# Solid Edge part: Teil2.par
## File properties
Author: administrator
Template: Normal.par
Last saved by: administrator
Revision: 1
Application: Solid Edge
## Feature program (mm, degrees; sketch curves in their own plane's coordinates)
sketch for "unnamed Protrusion 1" plane through (0, 0, 0) normal (0, -1, 0) x-axis (1, 0, 0)
  line (-30.1467, -35.4667) -> (-0.1467, -35.4667)
  line (-0.1467, -35.4667) -> (-0.1467, 4.5333)
  line (-0.1467, 4.5333) -> (-30.1467, 4.5333)
  line (-30.1467, 4.5333) -> (-30.1467, -35.4667)
extrude "unnamed Protrusion 1" add finite 40 symmetric
